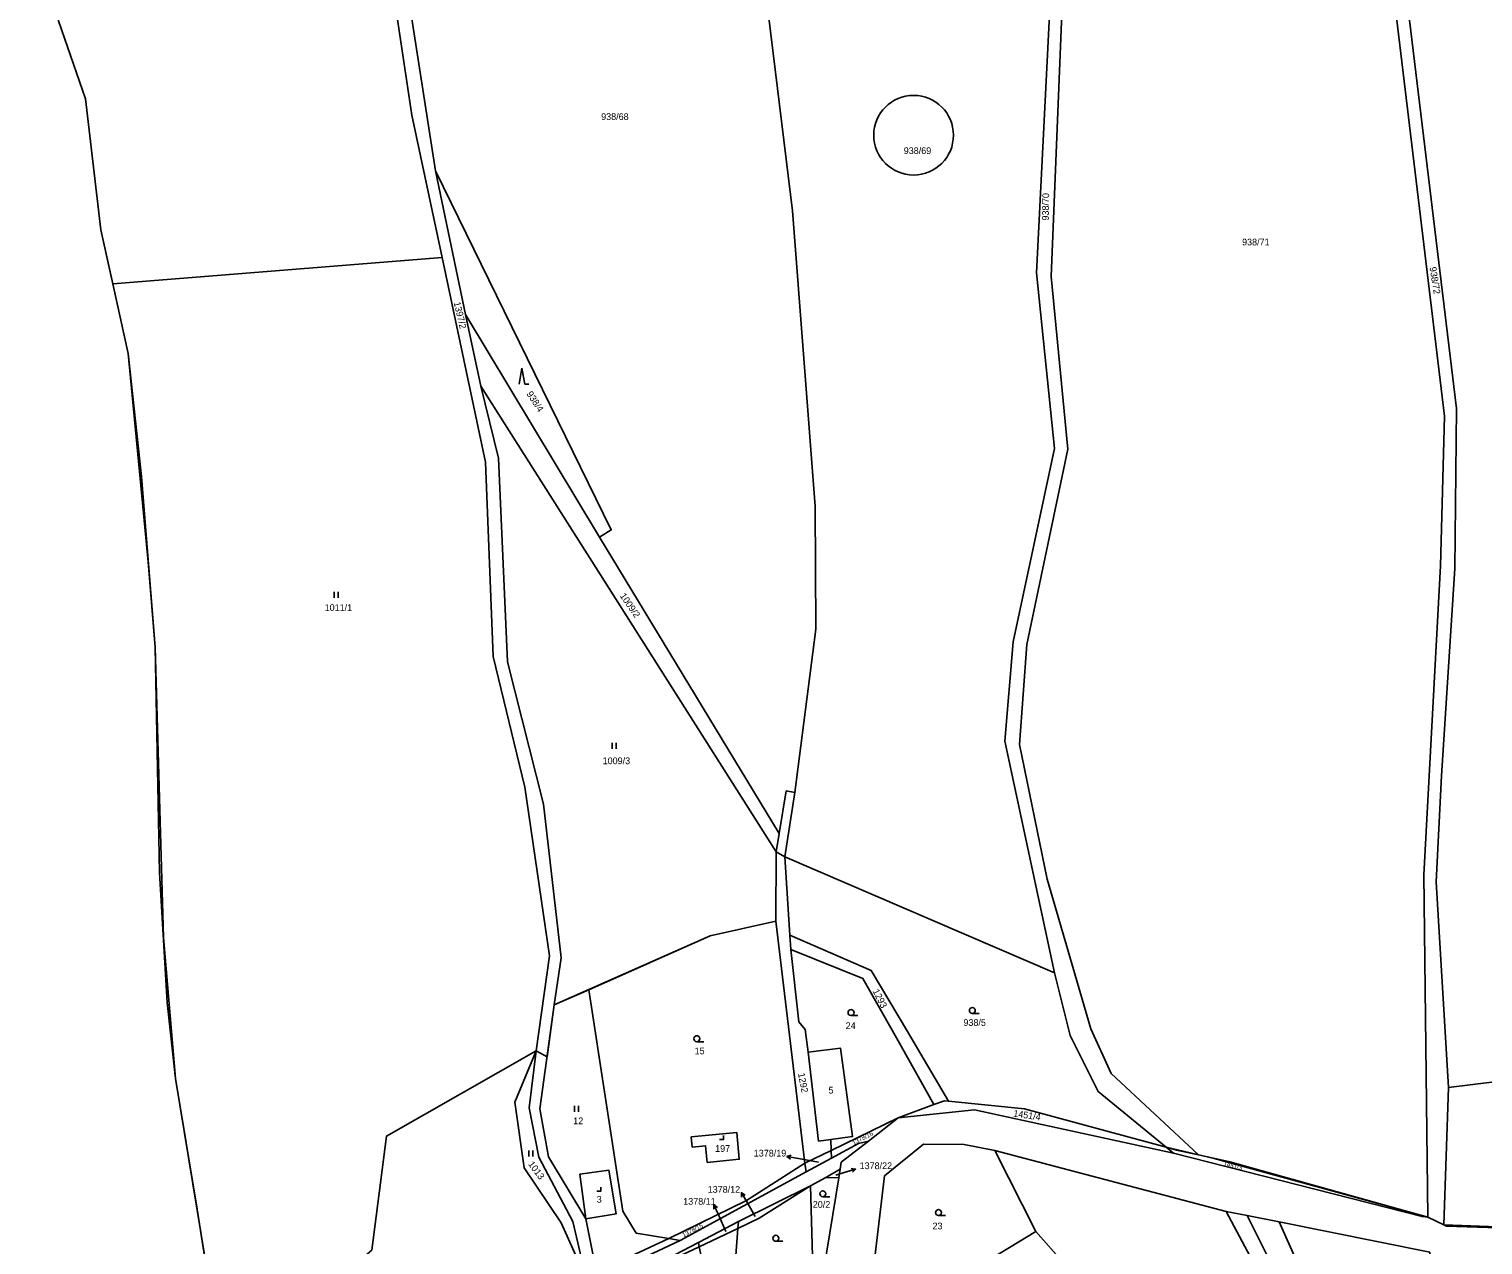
# Model space of a CAD drawing. Extents: x -588699 to -585793, y -1060280 to -1056731.
# Drawn here: x -588488.2 to -588120.4, y -1058115.3 to -1057807.9 of the extents above; entities that cross this region are included whole.
import ezdxf

# ---------------------------------------------------------------- set-up
doc = ezdxf.new("R2010")
doc.units = 0
for name, color, linetype in [('Druh pozemku', 7, 'Continuous'), ('Lesy', 7, 'Continuous'), ('Parcela nároku', 7, 'Continuous'), ('Parcelní číslo', 7, 'Continuous'), ('Vnější hranice převzatá', 7, 'Continuous'), ('Změna katastrální hranice', 7, 'Continuous')]:
    doc.layers.add(name, color=color, linetype=linetype)

msp = doc.modelspace()

# ---------------------------------------------------------------- linework, layer by layer
at = {"layer": 'Druh pozemku'}
for p, q in [((-588363.51, -1057893.63), (-588364.24, -1057897.63)), ((-588363.51, -1057893.63), (-588362.78, -1057897.63)), ((-588362.78, -1057897.63), (-588361.78, -1057897.63)), ((-588411.06, -1057950.15), (-588411.06, -1057951.65)), ((-588410.04, -1057951.65), (-588410.04, -1057950.15)), ((-588340.71, -1057988.35), (-588340.71, -1057989.85)), ((-588339.69, -1057989.85), (-588339.69, -1057988.35)), ((-588278.52, -1058057.3), (-588280.27, -1058057.3)), ((-588247.84, -1058056.76), (-588249.59, -1058056.76)), ((-588317.54, -1058063.91), (-588319.29, -1058063.91)), ((-588350.2, -1058080.14), (-588350.2, -1058081.64)), ((-588349.18, -1058081.64), (-588349.18, -1058080.14)), ((-588361.78, -1058091.41), (-588361.78, -1058092.91)), ((-588360.76, -1058092.91), (-588360.76, -1058091.41)), ((-588285.67, -1058103.12), (-588287.42, -1058103.12)), ((-588256.4, -1058107.88), (-588258.15, -1058107.88)), ((-588297.53, -1058114.38), (-588299.28, -1058114.38))]:
    msp.add_line(p, q, dxfattribs=at)
for points in [[(-588313.57, -1058088.67), (-588312.57, -1058088.67), (-588312.57, -1058087.67)], [(-588344.56, -1058101.69), (-588343.56, -1058101.69), (-588343.56, -1058100.69)]]:
    msp.add_lwpolyline(points, dxfattribs=at)
for centre in [(-588280.27, -1058056.55), (-588249.59, -1058056.01), (-588319.29, -1058063.16), (-588287.42, -1058102.37), (-588258.15, -1058107.13), (-588299.28, -1058113.63)]:
    msp.add_circle(centre, 0.75, dxfattribs=at)
at = {"layer": 'Lesy'}
for p, q in [((-588299.26, -1058033.45), (-588299.24, -1058015.87)), ((-588299.24, -1058015.87), (-588297.05, -1058017.2)), ((-588297.05, -1058017.2), (-588228.84, -1058046.46)), ((-588315.94, -1058037.15), (-588299.26, -1058033.45)), ((-588355.38, -1058054.63), (-588315.94, -1058037.15)), ((-588228.84, -1058046.46), (-588224.82, -1058062.35)), ((-588357.18, -1058067.76), (-588355.38, -1058054.63)), ((-588224.82, -1058062.35), (-588217.78, -1058076.52)), ((-588397.81, -1058087.8), (-588359.94, -1058066.21)), ((-588359.94, -1058066.21), (-588357.18, -1058067.76)), ((-588217.78, -1058076.52), (-588200.55, -1058090.62)), ((-588401.51, -1058116.63), (-588397.81, -1058087.8)), ((-588200.55, -1058090.62), (-588188.42, -1058093.41)), ((-588188.42, -1058093.41), (-588134.39, -1058108.31)), ((-588134.39, -1058108.31), (-588130.29, -1058110.23)), ((-588130.29, -1058110.23), (-588069.32, -1058112.52))]:
    msp.add_line(p, q, dxfattribs=at)
at = {"layer": 'Parcela nároku'}
for points in [[(-588146.85, -1057654), (-588083.68, -1057635.65), (-588081.67, -1057721.71), (-588069.75, -1057891.27), (-588068.25, -1058068.03), (-588129.14, -1058075.51), (-588132.27, -1058023.47), (-588130.87, -1057996.67), (-588127.55, -1057944.29), (-588127.1, -1057903.81), (-588141.26, -1057786.74), (-588142.09, -1057762.75), (-588146.38, -1057724.97)], [(-588134.39, -1058108.31), (-588135.39, -1058021.69), (-588131.14, -1057943.61), (-588130.13, -1057905.72), (-588144.22, -1057788.72), (-588145.81, -1057761.9), (-588149.72, -1057725.84), (-588149.64, -1057654.81), (-588223.44, -1057676.26), (-588221.96, -1057741.79), (-588225.65, -1057772.63), (-588229.67, -1057870.41), (-588225.43, -1057914.08), (-588235.81, -1057963.5), (-588237.67, -1057988.79), (-588230.7, -1058022.81), (-588219.63, -1058060.66), (-588214.5, -1058071.94), (-588192.36, -1058092.55), (-588184.47, -1058094.26)], [(-588142.09, -1057762.75), (-588141.26, -1057786.74), (-588127.1, -1057903.81), (-588127.55, -1057944.29), (-588130.87, -1057996.67), (-588132.27, -1058023.47), (-588129.14, -1058075.51), (-588130.29, -1058110.23), (-588134.39, -1058108.31), (-588135.39, -1058021.69), (-588131.14, -1057943.61), (-588130.13, -1057905.72), (-588144.22, -1057788.72), (-588145.81, -1057761.9), (-588149.72, -1057725.84), (-588149.64, -1057654.81), (-588146.85, -1057654), (-588146.38, -1057724.97)], [(-588214.5, -1058071.94), (-588192.36, -1058092.55), (-588197.92, -1058091.34), (-588200.55, -1058090.62), (-588217.78, -1058076.52), (-588224.82, -1058062.35), (-588228.84, -1058046.46), (-588241.33, -1057987.93), (-588239.28, -1057962.83), (-588228.78, -1057913.89), (-588233.36, -1057869.52), (-588228.44, -1057772.41), (-588224.87, -1057742.8), (-588226.2, -1057677.06), (-588223.44, -1057676.26), (-588221.96, -1057741.79), (-588225.65, -1057772.63), (-588229.67, -1057870.41), (-588225.43, -1057914.08), (-588235.81, -1057963.5), (-588237.67, -1057988.79), (-588230.7, -1058022.81), (-588219.63, -1058060.66)], [(-588313.6, -1057702.54), (-588226.2, -1057677.06), (-588224.87, -1057742.8), (-588228.44, -1057772.41), (-588233.36, -1057869.52), (-588228.78, -1057913.89), (-588239.28, -1057962.83), (-588241.33, -1057987.93), (-588228.84, -1058046.46), (-588297.05, -1058017.2), (-588294.5, -1058000.9), (-588289.2, -1057959.57), (-588289.31, -1057928.5), (-588295.09, -1057853.82)], [(-588289.2, -1057959.57), (-588294.5, -1058000.9), (-588296.65, -1058000.51), (-588298.47, -1058011.31), (-588343.9, -1057936.37), (-588340.95, -1057934.52), (-588385.37, -1057843.74), (-588392.82, -1057795.96), (-588395.89, -1057726.98), (-588313.6, -1057702.54), (-588295.09, -1057853.82), (-588289.31, -1057928.5)], [(-588485.36, -1057767.79), (-588485.22, -1057776.26), (-588480.77, -1057805.79), (-588473.95, -1057825.52), (-588470.06, -1057858.58), (-588467.62, -1057869.66), (-588467.05, -1057872.25), (-588383.72, -1057865.58), (-588391.36, -1057829.63), (-588395.96, -1057799.19), (-588399.32, -1057727.7), (-588488.2, -1057752.78)], [(-588385.37, -1057843.74), (-588340.95, -1057934.52), (-588343.9, -1057936.37), (-588377.82, -1057880.04)], [(-588453.26, -1058054.02), (-588451.16, -1058073.18), (-588440.27, -1058139.29), (-588439.11, -1058148.54), (-588401.51, -1058116.63), (-588397.81, -1058087.8), (-588359.94, -1058066.21), (-588356.56, -1058042.23), (-588362.75, -1057999.58), (-588370.81, -1057966.5), (-588372.71, -1057917.38), (-588383.72, -1057865.58), (-588467.05, -1057872.25), (-588463.17, -1057889.9), (-588459.8, -1057921.01), (-588456.31, -1057964.19), (-588455.18, -1058021.15)], [(-588343.9, -1057936.37), (-588298.47, -1058011.31), (-588299.24, -1058015.87), (-588373.9, -1057898.18), (-588377.82, -1057880.04)], [(-588355.38, -1058054.63), (-588353.56, -1058042.72), (-588358.1, -1058003.89), (-588367.14, -1057967.84), (-588369.44, -1057916.32), (-588373.9, -1057898.18), (-588299.24, -1058015.87), (-588299.26, -1058033.45), (-588315.94, -1058037.15), (-588346.56, -1058050.77)], [(-588297.05, -1058017.2), (-588295.72, -1058036.97), (-588295.48, -1058040.56), (-588293.44, -1058058.86), (-588291.87, -1058060.8), (-588291.14, -1058066.53), (-588288.49, -1058089.03), (-588285.38, -1058088.63), (-588285.3, -1058091.4), (-588291.93, -1058094.66), (-588299.26, -1058033.45), (-588299.24, -1058015.87), (-588298.47, -1058011.31), (-588296.65, -1058000.51), (-588294.5, -1058000.9)], [(-588297.05, -1058017.2), (-588228.84, -1058046.46), (-588224.82, -1058062.35), (-588217.78, -1058076.52), (-588200.55, -1058090.62), (-588236.38, -1058080.86), (-588255.63, -1058078.96), (-588266, -1058061.36), (-588275.18, -1058045.88), (-588295.72, -1058036.97)], [(-588315.94, -1058037.15), (-588346.56, -1058050.77), (-588338.01, -1058106.78), (-588334.59, -1058112.33), (-588326.35, -1058113.66), (-588306.68, -1058104.06), (-588291.93, -1058094.66), (-588299.26, -1058033.45)], [(-588266, -1058061.36), (-588275.18, -1058045.88), (-588295.72, -1058036.97), (-588295.48, -1058040.56), (-588277.28, -1058047.95), (-588268.8, -1058062.96), (-588259.29, -1058079.83), (-588256.59, -1058078.87), (-588255.63, -1058078.96)], [(-588277.28, -1058047.95), (-588268.8, -1058062.96), (-588259.29, -1058079.83), (-588268.33, -1058083.17), (-588285.3, -1058091.4), (-588285.38, -1058088.63), (-588279.88, -1058087.91), (-588282.92, -1058065.59), (-588291.14, -1058066.53), (-588291.87, -1058060.8), (-588293.44, -1058058.86), (-588295.48, -1058040.56)], [(-588347.34, -1058108.72), (-588344.7, -1058122.22), (-588326.35, -1058113.66), (-588334.59, -1058112.33), (-588338.01, -1058106.78), (-588346.56, -1058050.77), (-588355.38, -1058054.63), (-588358.98, -1058080.9), (-588356.77, -1058093.01)], [(-588359.94, -1058066.21), (-588397.81, -1058087.8), (-588401.51, -1058116.63), (-588439.11, -1058148.54), (-588437.6, -1058160.57), (-588436.28, -1058183.04), (-588420.67, -1058183.06), (-588393.33, -1058163.66), (-588380.84, -1058152.03), (-588369.96, -1058137.69), (-588347.27, -1058123.79), (-588353.6, -1058109.72), (-588362.96, -1058095.84), (-588365.29, -1058079.2)], [(-588365.29, -1058079.2), (-588359.94, -1058066.21), (-588361.73, -1058080.68), (-588359.23, -1058093.11), (-588350.63, -1058109.41), (-588347.27, -1058123.79), (-588353.6, -1058109.72), (-588362.96, -1058095.84)], [(-588282.92, -1058065.59), (-588291.14, -1058066.53), (-588288.49, -1058089.03), (-588285.38, -1058088.63), (-588279.88, -1058087.91)], [(-588068.25, -1058068.03), (-588067.88, -1058079.03), (-588068.33, -1058085.63), (-588069.32, -1058112.52), (-588129.61, -1058110.55), (-588130.29, -1058110.23), (-588129.14, -1058075.51)], [(-588236.38, -1058080.86), (-588200.55, -1058090.62), (-588198.72, -1058092.12), (-588249.06, -1058081.13), (-588268.33, -1058083.17), (-588259.29, -1058079.83), (-588256.59, -1058078.87), (-588255.63, -1058078.96)], [(-588285.3, -1058091.4), (-588268.33, -1058083.17), (-588275.87, -1058089.04), (-588278.4, -1058089.63), (-588285.24, -1058093.35)], [(-588320.7, -1058088.01), (-588309.19, -1058086.91), (-588308.56, -1058093.66), (-588316.66, -1058094.43), (-588317.06, -1058090.21), (-588320.45, -1058090.55)], [(-588317.06, -1058090.21), (-588320.45, -1058090.55), (-588320.7, -1058088.01), (-588309.19, -1058086.91), (-588308.56, -1058093.66), (-588316.66, -1058094.43)], [(-588291.93, -1058094.66), (-588285.3, -1058091.4), (-588285.24, -1058093.35), (-588291.66, -1058096.83)], [(-588251.63, -1058089.93), (-588243.9, -1058091.45), (-588233.5, -1058111.89), (-588255.46, -1058125.26), (-588257.55, -1058129.34), (-588263.75, -1058141.47), (-588276.82, -1058139.7), (-588271.78, -1058097.87), (-588261.94, -1058089.86)], [(-588185.34, -1058106.83), (-588243.9, -1058091.45), (-588233.5, -1058111.89), (-588220.72, -1058126.38), (-588187, -1058161.78), (-588151.89, -1058174.08), (-588153.74, -1058161.51), (-588172.49, -1058131.01)], [(-588192.36, -1058092.55), (-588184.47, -1058094.26), (-588134.39, -1058108.31), (-588135.81, -1058108.15), (-588198.72, -1058092.12), (-588200.55, -1058090.62), (-588197.92, -1058091.34)], [(-588291.93, -1058094.66), (-588306.68, -1058104.06), (-588326.35, -1058113.66), (-588323.52, -1058114.21), (-588291.66, -1058096.83)], [(-588286.65, -1058098.25), (-588283.01, -1058096.11), (-588283.37, -1058098.3)], [(-588341.52, -1058096.43), (-588339.67, -1058107.43), (-588347.34, -1058108.72), (-588348.91, -1058097.45)], [(-588347.34, -1058108.72), (-588348.91, -1058097.45), (-588341.52, -1058096.43), (-588339.67, -1058107.43)], [(-588290.51, -1058100.34), (-588286.65, -1058098.25), (-588283.37, -1058098.3), (-588289.55, -1058135.97), (-588289.87, -1058124.16)], [(-588309.93, -1058124.83), (-588308.87, -1058111.13), (-588303.49, -1058108.58), (-588290.51, -1058100.34), (-588289.87, -1058124.16)], [(-588308.74, -1058109.42), (-588290.51, -1058100.34), (-588303.49, -1058108.58), (-588308.87, -1058111.13)], [(-588150.93, -1058159.62), (-588170.57, -1058126.95), (-588180.09, -1058107.88), (-588185.34, -1058106.83), (-588172.49, -1058131.01), (-588153.74, -1058161.51), (-588149.53, -1058173.07)], [(-588318.89, -1058114.72), (-588308.74, -1058109.42), (-588308.87, -1058111.13), (-588318.67, -1058115.77)], [(-588150.93, -1058159.62), (-588150.98, -1058156.5), (-588151.05, -1058151.7), (-588149.8, -1058146.94), (-588167.54, -1058119.5), (-588172.01, -1058109.5), (-588180.09, -1058107.88), (-588170.57, -1058126.95)], [(-588133.87, -1058117.14), (-588172.01, -1058109.5), (-588167.54, -1058119.5), (-588149.8, -1058146.94), (-588148.76, -1058143.01), (-588140.51, -1058138.04), (-588133.9, -1058127.64)], [(-588323.52, -1058114.21), (-588326.35, -1058113.66), (-588344.7, -1058122.22), (-588344.31, -1058123.97)], [(-588308.87, -1058111.13), (-588318.67, -1058115.77), (-588316.7, -1058125.06), (-588309.93, -1058124.83)], [(-588233.5, -1058111.89), (-588220.72, -1058126.38), (-588187, -1058161.78), (-588186.48, -1058166.56), (-588187.86, -1058166.8), (-588187.14, -1058173.38), (-588195.16, -1058174.34), (-588173.47, -1058255.38), (-588188.13, -1058265.89), (-588195.07, -1058269.17), (-588225.24, -1058292.17), (-588257.55, -1058129.34), (-588255.46, -1058125.26)], [(-588342.77, -1058127.18), (-588318.89, -1058114.72), (-588318.67, -1058115.77)]]:
    msp.add_lwpolyline(points, close=True, dxfattribs=at)
for points in [[(-588344.7, -1058122.22), (-588347.34, -1058108.72), (-588356.77, -1058093.01), (-588358.98, -1058080.9), (-588355.38, -1058054.63), (-588353.56, -1058042.72), (-588358.1, -1058003.89), (-588367.14, -1057967.84), (-588369.44, -1057916.32), (-588373.9, -1057898.18), (-588377.82, -1057880.04), (-588385.37, -1057843.74), (-588392.82, -1057795.96)], [(-588395.96, -1057799.19), (-588391.36, -1057829.63), (-588383.72, -1057865.58), (-588372.71, -1057917.38), (-588370.81, -1057966.5), (-588362.75, -1057999.58), (-588356.56, -1058042.23), (-588359.94, -1058066.21), (-588361.73, -1058080.68), (-588359.23, -1058093.11), (-588350.63, -1058109.41), (-588347.27, -1058123.79)], [(-588289.55, -1058135.97), (-588283.37, -1058098.3), (-588283.01, -1058096.11), (-588282.73, -1058094.39), (-588275.87, -1058089.04), (-588268.33, -1058083.17), (-588249.06, -1058081.13), (-588198.72, -1058092.12), (-588135.81, -1058108.15), (-588134.39, -1058108.31), (-588130.29, -1058110.23), (-588129.61, -1058110.55), (-588069.32, -1058112.52), (-588049.75, -1058113.96), (-588027.63, -1058113), (-588017.89, -1058112.74), (-588008.77, -1058113.8), (-588003.37, -1058114.43), (-588000.59, -1058114.37), (-587982.29, -1058114.31), (-587972.07, -1058115), (-587958.19, -1058116.05)], [(-588344.31, -1058123.97), (-588323.52, -1058114.21), (-588291.66, -1058096.83), (-588285.24, -1058093.35), (-588278.4, -1058089.63), (-588275.87, -1058089.04), (-588282.73, -1058094.39), (-588283.01, -1058096.11), (-588286.65, -1058098.25), (-588290.51, -1058100.34), (-588308.74, -1058109.42), (-588318.89, -1058114.72), (-588342.77, -1058127.18)], [(-588133.87, -1058117.14), (-588172.01, -1058109.5), (-588180.09, -1058107.88), (-588185.34, -1058106.83), (-588243.9, -1058091.45), (-588251.63, -1058089.93), (-588261.94, -1058089.86), (-588271.78, -1058097.87), (-588276.82, -1058139.7)]]:
    msp.add_lwpolyline(points, dxfattribs=at)
at = {"layer": 'Parcelní číslo'}
for p, q in [((-588293.54, -1058093.49), (-588296.49, -1058092.95)), ((-588288.54, -1058094.41), (-588293.54, -1058093.49)), ((-588281.98, -1058097), (-588279.11, -1058096.14)), ((-588284.13, -1058097.65), (-588281.98, -1058097)), ((-588306.49, -1058104.7), (-588308.02, -1058102.12)), ((-588313.72, -1058107.88), (-588314.94, -1058105.14)), ((-588304.49, -1058108.09), (-588306.49, -1058104.7)), ((-588311.92, -1058111.92), (-588313.72, -1058107.88))]:
    msp.add_line(p, q, dxfattribs=at)
for points in [[(-588295.6, -1058093.62), (-588296.49, -1058092.95), (-588295.42, -1058092.64)], [(-588280.21, -1058095.95), (-588279.11, -1058096.14), (-588279.92, -1058096.9)], [(-588307.94, -1058103.23), (-588308.02, -1058102.12), (-588307.08, -1058102.72)], [(-588314.99, -1058106.26), (-588314.94, -1058105.14), (-588314.08, -1058105.85)]]:
    msp.add_lwpolyline(points, dxfattribs=at)
at = {"layer": 'Vnější hranice převzatá'}
for p, q in [((-588480.77, -1057805.79), (-588473.95, -1057825.52)), ((-588473.95, -1057825.52), (-588470.06, -1057858.58)), ((-588470.06, -1057858.58), (-588467.05, -1057872.25)), ((-588467.05, -1057872.25), (-588463.17, -1057889.9)), ((-588463.17, -1057889.9), (-588458.06, -1057942.6)), ((-588458.06, -1057942.6), (-588456.31, -1057964.19)), ((-588456.31, -1057964.19), (-588454.22, -1058037.58)), ((-588454.22, -1058037.58), (-588451.16, -1058073.18)), ((-588451.16, -1058073.18), (-588445.72, -1058106.24)), ((-588445.72, -1058106.24), (-588439.11, -1058148.54))]:
    msp.add_line(p, q, dxfattribs=at)
at = {"layer": 'Změna katastrální hranice'}
msp.add_circle((-588264.44, -1057834.69), 10.08, dxfattribs=at)

# ---------------------------------------------------------------- texts
at = {"layer": 'Parcela nároku'}
for s, height, p in [('938/68', 1.7, (-588343.48, -1057830.84)), ('938/69', 1.7, (-588266.94, -1057839.46)), ('938/71', 1.7, (-588181.35, -1057862.56)), ('1011/1', 1.7, (-588413.43, -1057955)), ('1009/3', 1.7, (-588343.11, -1057993.74)), ('24', 1.7, (-588281.62, -1058060.71)), ('938/5', 1.7, (-588251.85, -1058059.92)), ('15', 1.7, (-588319.85, -1058067.09)), ('5', 1.7, (-588285.97, -1058077.02)), ('12', 1.7, (-588350.55, -1058084.78)), ('197', 1.7, (-588314.65, -1058091.77)), ('1378/19', 0.1, (-588288.76, -1058094.41)), ('1378/22', 0.1, (-588284.37, -1058097.65)), ('3', 1.7, (-588344.61, -1058104.62)), ('20/2', 1.7, (-588289.95, -1058105.92)), ('1378/12', 0.1, (-588304.71, -1058108.09)), ('23', 1.7, (-588259.67, -1058111.36)), ('1378/11', 0.1, (-588312.12, -1058111.92))]:
    msp.add_text(s, height=height, dxfattribs=at).set_placement(p)
for s, height, rotation, p in [('938/70', 1.7, 89.0422, (-588230.26, -1057856.29)), ('938/72', 1.7, 279.0966, (-588133.93, -1057868.13)), ('1397/2', 1.7, 283.148, (-588380.78, -1057877.02)), ('938/4', 1.7, 303.012, (-588362.43, -1057900.1)), ('1009/2', 1.7, 304.6811, (-588338.84, -1057951.18)), ('1293', 1.7, 297.1112, (-588274.86, -1058051.12)), ('1292', 1.7, 280.8898, (-588293.7, -1058071.97)), ('1451/4', 1.7, 351.5414, (-588239.31, -1058082.83)), ('1378/16', 1.14, 27.9634, (-588279.57, -1058090.12)), ('1013', 1.7, 306.3648, (-588362.04, -1058094.89)), ('1451/3', 1.14, 346.0205, (-588186.16, -1058095.22)), ('1378/15', 1.14, 27.1081, (-588322.61, -1058113.4))]:
    msp.add_text(s, height=height, rotation=rotation, dxfattribs=at).set_placement(p)
at = {"layer": 'Parcelní číslo'}
for s, p in [('1378/19', (-588304.88, -1058092.95)), ('1378/22', (-588278.11, -1058096.14)), ('1378/11', (-588322.72, -1058105.14)), ('1378/12', (-588316.54, -1058102.12))]:
    msp.add_text(s, height=1.7, dxfattribs=at).set_placement(p)

doc.saveas('drawing.dxf')
